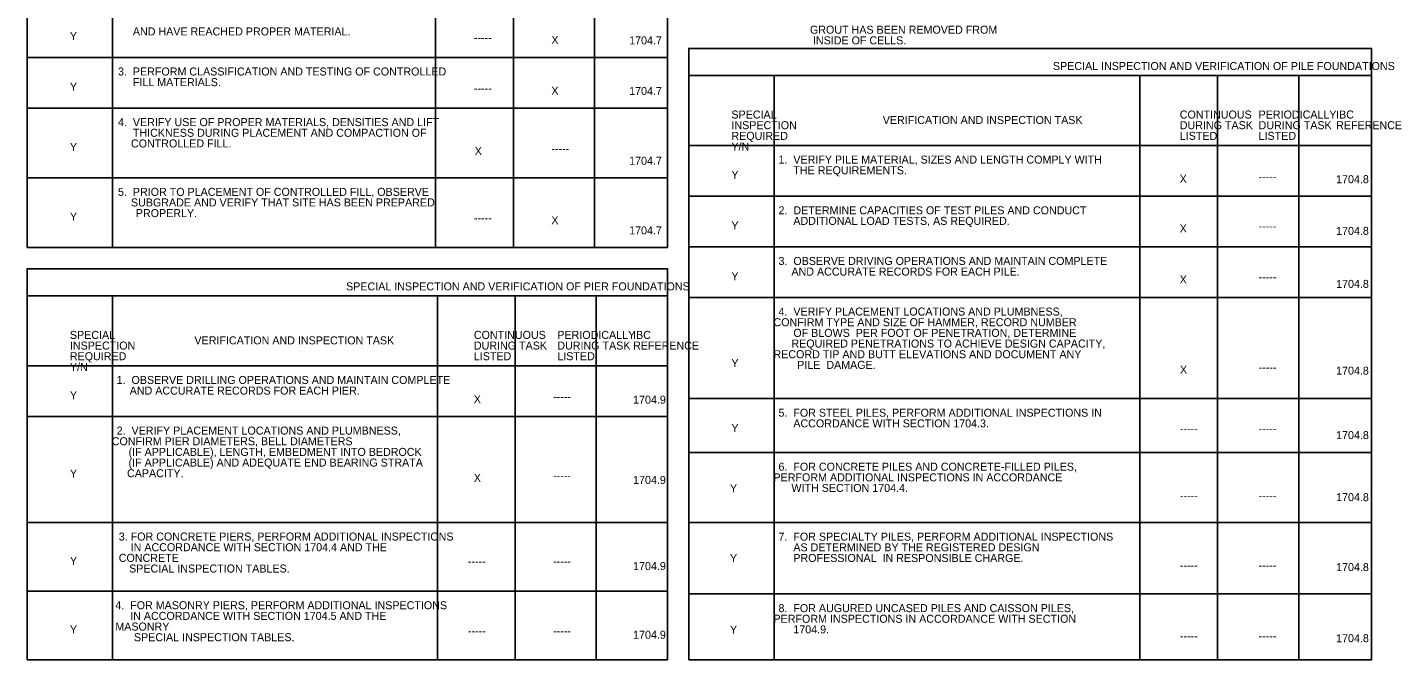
# Model space of a CAD drawing. Extents: x 2632118 to 2632142.4, y 1706724.1 to 1706788.4.
# Drawn here: x 2632120.7 to 2632134.87, y 1706748.45 to 1706755.03 of the extents above; entities that cross this region are included whole.
import ezdxf

# ---------------------------------------------------------------- set-up
doc = ezdxf.new("R2010")
doc.units = 0
doc.layers.add('Default', color=7, linetype='Continuous')

msp = doc.modelspace()

# ---------------------------------------------------------------- linework, layer by layer
at = {"layer": 'Default'}
for p, q in [((2632121.588, 1706756.499), (2632121.588, 1706752.738)), ((2632124.953, 1706756.499), (2632124.953, 1706752.738)), ((2632125.762, 1706756.499), (2632125.762, 1706752.738)), ((2632126.608, 1706756.499), (2632126.608, 1706752.738)), ((2632127.366, 1706754.716), (2632120.699, 1706754.716)), ((2632128.477, 1706754.527), (2632128.477, 1706748.446)), ((2632132.287, 1706754.527), (2632132.287, 1706748.446)), ((2632133.096, 1706754.527), (2632133.096, 1706748.446)), ((2632133.941, 1706754.527), (2632133.941, 1706748.446)), ((2632127.366, 1706754.189), (2632120.699, 1706754.189)), ((2632134.699, 1706753.799), (2632127.588, 1706753.799)), ((2632127.366, 1706753.464), (2632120.699, 1706753.464)), ((2632134.699, 1706753.272), (2632127.588, 1706753.272)), ((2632134.699, 1706752.744), (2632127.588, 1706752.744)), ((2632121.588, 1706752.234), (2632121.588, 1706748.446)), ((2632124.972, 1706752.234), (2632124.972, 1706748.446)), ((2632125.781, 1706752.234), (2632125.781, 1706748.446)), ((2632126.626, 1706752.234), (2632126.626, 1706748.446)), ((2632134.699, 1706752.217), (2632127.588, 1706752.217)), ((2632126.141, 1706751.505), (2632120.699, 1706751.505)), ((2632126.141, 1706751.505), (2632127.366, 1706751.505)), ((2632134.699, 1706751.164), (2632127.588, 1706751.164)), ((2632127.366, 1706750.978), (2632120.699, 1706750.978)), ((2632134.699, 1706750.603), (2632127.588, 1706750.603)), ((2632127.366, 1706749.875), (2632120.699, 1706749.875)), ((2632134.699, 1706749.874), (2632127.588, 1706749.874)), ((2632127.366, 1706749.16), (2632120.699, 1706749.16)), ((2632134.699, 1706749.131), (2632127.588, 1706749.131))]:
    msp.add_line(p, q, dxfattribs=at)
for points in [[(2632120.699, 1706752.738), (2632127.366, 1706752.738), (2632127.366, 1706756.782), (2632120.699, 1706756.782)], [(2632127.588, 1706748.446), (2632134.699, 1706748.446), (2632134.699, 1706754.81), (2632127.588, 1706754.81)], [(2632120.699, 1706748.446), (2632127.366, 1706748.446), (2632127.366, 1706752.516), (2632120.699, 1706752.516)]]:
    msp.add_lwpolyline(points, close=True, dxfattribs=at)
for points in [[(2632134.699, 1706754.527), (2632127.588, 1706754.527)], [(2632127.366, 1706752.234), (2632120.699, 1706752.234)]]:
    msp.add_lwpolyline(points, dxfattribs=at)

# ---------------------------------------------------------------- texts
for s, height, p in [('Y', 0.0833, (2632121.144, 1706754.897)), ('     AND HAVE REACHED PROPER MATERIAL.', 0.08333, (2632121.645, 1706754.945)), ('    GROUT HAS BEEN REMOVED FROM ', 0.08333, (2632128.727, 1706754.963)), ('-----', 0.0833, (2632125.351, 1706754.881)), ('X', 0.0833, (2632126.158, 1706754.856)), ('1704.7', 0.0833, (2632126.968, 1706754.852)), ('    INSIDE OF CELLS.', 0.08333, (2632128.758, 1706754.852)), ('SPECIAL INSPECTION AND VERIFICATION OF PILE FOUNDATIONS', 0.08333, (2632131.381, 1706754.585)), ('3.  PERFORM CLASSIFICATION AND TESTING OF CONTROLLED', 0.08333, (2632121.645, 1706754.528)), ('Y', 0.0833, (2632121.144, 1706754.369)), ('     FILL MATERIALS.', 0.08333, (2632121.645, 1706754.417)), ('-----', 0.0833, (2632125.351, 1706754.354)), ('X', 0.0833, (2632126.158, 1706754.328)), ('1704.7', 0.0833, (2632126.968, 1706754.325)), ('SPECIAL ', 0.0833, (2632128.033, 1706754.08)), ('VERIFICATION AND INSPECTION TASK ', 0.08333, (2632129.609, 1706754.023)), ('CONTINUOUS ', 0.08333, (2632132.702, 1706754.08)), ('PERIODICALLY ', 0.08333, (2632133.523, 1706754.08)), ('IBC ', 0.0833, (2632134.33, 1706754.08)), ('4.  VERIFY USE OF PROPER MATERIALS, DENSITIES AND LIFT', 0.08333, (2632121.645, 1706754.001)), ('     THICKNESS DURING PLACEMENT AND COMPACTION OF ', 0.08333, (2632121.645, 1706753.89)), ('INSPECTION ', 0.08333, (2632128.033, 1706753.969)), ('DURING TASK ', 0.08333, (2632132.702, 1706753.969)), ('DURING TASK ', 0.08333, (2632133.523, 1706753.969)), ('REFERENCE', 0.0833, (2632134.33, 1706753.969)), ('Y', 0.0833, (2632121.144, 1706753.743)), ('     CONTROLLED FILL. ', 0.08333, (2632121.625, 1706753.779)), ('Y/N', 0.0833, (2632128.033, 1706753.747)), ('REQUIRED', 0.0833, (2632128.033, 1706753.858)), ('LISTED ', 0.0833, (2632132.702, 1706753.858)), ('LISTED ', 0.0833, (2632133.523, 1706753.858)), ('X', 0.0833, (2632125.36, 1706753.701)), ('-----', 0.0833, (2632126.158, 1706753.726)), ('1704.7', 0.0833, (2632126.968, 1706753.599)), ('1.  VERIFY PILE MATERIAL, SIZES AND LENGTH COMPLY WITH', 0.08333, (2632128.523, 1706753.611)), ('Y', 0.0833, (2632128.033, 1706753.452)), ('     THE REQUIREMENTS.', 0.08333, (2632128.523, 1706753.5)), ('X', 0.0833, (2632132.701, 1706753.411)), ('-----', 0.0833, (2632133.523, 1706753.436)), ('1704.8', 0.0833, (2632134.33, 1706753.407)), ('5.  PRIOR TO PLACEMENT OF CONTROLLED FILL, OBSERVE', 0.08333, (2632121.645, 1706753.275)), ('     SUBGRADE AND VERIFY THAT SITE HAS BEEN PREPARED', 0.08333, (2632121.625, 1706753.165)), ('      PROPERLY.', 0.08333, (2632121.645, 1706753.054)), ('2.  DETERMINE CAPACITIES OF TEST PILES AND CONDUCT', 0.08333, (2632128.523, 1706753.083)), ('Y', 0.0833, (2632121.144, 1706753.018)), ('-----', 0.0833, (2632125.351, 1706753.004)), ('X', 0.0833, (2632126.158, 1706752.979)), ('Y', 0.0833, (2632128.033, 1706752.925)), ('     ADDITIONAL LOAD TESTS, AS REQUIRED.', 0.08333, (2632128.523, 1706752.973)), ('X', 0.0833, (2632132.701, 1706752.894)), ('1704.7', 0.0833, (2632126.968, 1706752.874)), ('-----', 0.0833, (2632133.523, 1706752.919)), ('1704.8', 0.0833, (2632134.33, 1706752.869)), ('3.  OBSERVE DRIVING OPERATIONS AND MAINTAIN COMPLETE', 0.08333, (2632128.523, 1706752.556)), ('Y', 0.0833, (2632128.033, 1706752.397)), ('     AND ACCURATE RECORDS FOR EACH PILE.', 0.08333, (2632128.503, 1706752.445)), ('X', 0.0833, (2632132.701, 1706752.364)), ('-----', 0.0833, (2632133.523, 1706752.389)), ('1704.8', 0.0833, (2632134.33, 1706752.317)), ('SPECIAL INSPECTION AND VERIFICATION OF PIER FOUNDATIONS', 0.08333, (2632124.02, 1706752.291)), ('4.  VERIFY PLACEMENT LOCATIONS AND PLUMBNESS, ', 0.08333, (2632128.523, 1706752.029)), ('     CONFIRM TYPE AND SIZE OF HAMMER, RECORD NUMBER ', 0.08333, (2632128.316, 1706751.918)), ('SPECIAL ', 0.0833, (2632121.144, 1706751.786)), ('CONTINUOUS ', 0.08333, (2632125.351, 1706751.786)), ('PERIODICALLY ', 0.08333, (2632126.22, 1706751.786)), ('IBC ', 0.0833, (2632127.009, 1706751.786)), ('     OF BLOWS  PER FOOT OF PENETRATION, DETERMINE ', 0.08333, (2632128.523, 1706751.807)), ('INSPECTION ', 0.08333, (2632121.144, 1706751.675)), ('VERIFICATION AND INSPECTION TASK ', 0.08333, (2632122.441, 1706751.729)), ('DURING TASK ', 0.08333, (2632125.351, 1706751.675)), ('DURING TASK', 0.08333, (2632126.22, 1706751.675)), ('REFERENCE', 0.0833, (2632127.009, 1706751.675)), ('     REQUIRED PENETRATIONS TO ACHIEVE DESIGN CAPACITY, ', 0.08333, (2632128.503, 1706751.696)), ('REQUIRED', 0.0833, (2632121.144, 1706751.564)), ('LISTED ', 0.0833, (2632125.351, 1706751.564)), ('LISTED ', 0.0833, (2632126.22, 1706751.564)), ('Y', 0.0833, (2632128.033, 1706751.492)), ('     RECORD TIP AND BUTT ELEVATIONS AND DOCUMENT ANY ', 0.08333, (2632128.316, 1706751.585)), ('     PILE  DAMAGE. ', 0.08333, (2632128.563, 1706751.474)), ('Y/N', 0.0833, (2632121.144, 1706751.453)), ('X', 0.0833, (2632132.704, 1706751.424)), ('-----', 0.0833, (2632133.524, 1706751.45)), ('1704.8', 0.0833, (2632134.33, 1706751.414)), ('1.  OBSERVE DRILLING OPERATIONS AND MAINTAIN COMPLETE', 0.08333, (2632121.631, 1706751.317)), ('     AND ACCURATE RECORDS FOR EACH PIER.', 0.08333, (2632121.612, 1706751.206)), ('Y', 0.0833, (2632121.144, 1706751.158)), ('X', 0.0833, (2632125.35, 1706751.117)), ('-----', 0.0833, (2632126.176, 1706751.143)), ('1704.9', 0.0833, (2632127.009, 1706751.112)), ('5.  FOR STEEL PILES, PERFORM ADDITIONAL INSPECTIONS IN ', 0.08333, (2632128.523, 1706750.976)), ('2.  VERIFY PLACEMENT LOCATIONS AND PLUMBNESS, ', 0.08333, (2632121.631, 1706750.79)), ('Y', 0.0833, (2632128.033, 1706750.817)), ('     ACCORDANCE WITH SECTION 1704.3.', 0.08333, (2632128.523, 1706750.865)), ('-----', 0.0833, (2632132.704, 1706750.809)), ('-----', 0.0833, (2632133.523, 1706750.809)), ('     CONFIRM PIER DIAMETERS, BELL DIAMETERS ', 0.08333, (2632121.425, 1706750.679)), ('1704.8', 0.0833, (2632134.33, 1706750.743)), ('    (IF APPLICABLE), LENGTH, EMBEDMENT INTO BEDROCK', 0.08333, (2632121.631, 1706750.568)), ('Y', 0.0833, (2632121.144, 1706750.343)), ('    CAPACITY.', 0.08333, (2632121.615, 1706750.346)), ('    (IF APPLICABLE) AND ADEQUATE END BEARING STRATA', 0.08333, (2632121.631, 1706750.457)), ('6.  FOR CONCRETE PILES AND CONCRETE-FILLED PILES,', 0.08333, (2632128.523, 1706750.414)), ('X', 0.0833, (2632125.35, 1706750.298)), ('-----', 0.0833, (2632126.176, 1706750.323)), ('1704.9', 0.0833, (2632127.009, 1706750.276)), ('Y', 0.0833, (2632128.018, 1706750.19)), ('     PERFORM ADDITIONAL INSPECTIONS IN ACCORDANCE ', 0.08333, (2632128.316, 1706750.303)), ('     WITH SECTION 1704.4.', 0.08333, (2632128.503, 1706750.193)), ('-----', 0.0833, (2632132.704, 1706750.115)), ('-----', 0.0833, (2632133.523, 1706750.115)), ('1704.8', 0.0833, (2632134.33, 1706750.097)), ('3. FOR CONCRETE PIERS, PERFORM ADDITIONAL INSPECTIONS ', 0.08333, (2632121.653, 1706749.687)), ('7.  FOR SPECIALTY PILES, PERFORM ADDITIONAL INSPECTIONS', 0.08333, (2632128.523, 1706749.686)), ('    IN ACCORDANCE WITH SECTION 1704.4 AND THE ', 0.08333, (2632121.653, 1706749.576)), ('     AS DETERMINED BY THE REGISTERED DESIGN', 0.08333, (2632128.523, 1706749.575)), ('Y', 0.0833, (2632121.144, 1706749.434)), ('CONCRETE ', 0.0833, (2632121.653, 1706749.465)), ('    SPECIAL INSPECTION TABLES.', 0.08333, (2632121.637, 1706749.354)), ('-----', 0.0833, (2632125.289, 1706749.43)), ('-----', 0.0833, (2632126.176, 1706749.43)), ('1704.9', 0.0833, (2632127.009, 1706749.38)), ('Y', 0.0833, (2632128.018, 1706749.462)), ('     PROFESSIONAL  IN RESPONSIBLE CHARGE.', 0.08333, (2632128.523, 1706749.464)), ('-----', 0.0833, (2632132.704, 1706749.387)), ('-----', 0.0833, (2632133.523, 1706749.387)), ('1704.8', 0.0833, (2632134.33, 1706749.369)), ('4.  FOR MASONRY PIERS, PERFORM ADDITIONAL INSPECTIONS ', 0.08333, (2632121.617, 1706748.972)), ('8.  FOR AUGURED UNCASED PILES AND CAISSON PILES, ', 0.08333, (2632128.523, 1706748.942)), ('     IN ACCORDANCE WITH SECTION 1704.5 AND THE ', 0.08333, (2632121.617, 1706748.861)), ('     PERFORM INSPECTIONS IN ACCORDANCE WITH SECTION', 0.08333, (2632128.316, 1706748.831)), ('Y', 0.0833, (2632121.144, 1706748.72)), ('MASONRY', 0.0833, (2632121.617, 1706748.75)), ('     SPECIAL INSPECTION TABLES.', 0.08333, (2632121.656, 1706748.639)), ('-----', 0.0833, (2632125.289, 1706748.704)), ('-----', 0.0833, (2632126.176, 1706748.704)), ('1704.9', 0.0833, (2632127.009, 1706748.665)), ('Y', 0.0833, (2632128.018, 1706748.718)), ('     1704.9. ', 0.08333, (2632128.523, 1706748.721)), ('1704.8', 0.0833, (2632134.33, 1706748.629)), ('-----', 0.0833, (2632132.704, 1706748.652)), ('-----', 0.0833, (2632133.523, 1706748.652))]:
    msp.add_text(s, height=height, dxfattribs=at).set_placement(p)

doc.saveas('drawing.dxf')
